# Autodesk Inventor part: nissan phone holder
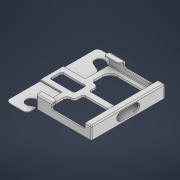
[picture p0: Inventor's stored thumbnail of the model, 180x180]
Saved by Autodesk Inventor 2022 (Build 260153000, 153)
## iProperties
Created: 2021-11
Part Number: nissan phone holder
Material: Všeobecné
Document SubType Name: Modeling
Designer: Fiji
Density: 1 g/cm^3
Appearance: Výchozí
Author: Fiji
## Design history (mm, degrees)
sketch "Náčrt1"
  geometry: L1 (0, 0)-(-22, 0); L2 (-22, 0)-(-22, -36); L3 (-22, -36)-(0, -36); L4 (0, -36)-(0, 0); L5 (-22, -11)-(-12.755, -5.4); L6 (-22, -21)-(-7.774, -14.716); C1 r 5 at (-14, -12); 2 further points
  constraints: 12 end point, 2 parallel, 2 point on line, 2 tangent, 1 centre point, 1 horizontal, 1 perpendicular
  dimensions: "d0" = 22 distance of L2.end L3.end; "d1" = 36 distance of L3.end L1.start; "d2" = 10 diameter of C1; "d3" = 12 distance from line of L1 C1.centre; "d4" = 8 distance from line of L2 C1.centre; "d5" = 11 distance from line of L1 L5.start; "d6" = 10 distance of L6.start L5.start
extrude "Vysunutí1" new body sketch "Náčrt1" distance "d7" = 0.6; taper "d8" = 0 deg
sketch "Náčrt2"
  geometry: L1 (-22, -36)-(0, -36) reference; L2 (0, -36)-(-22, -36); L3 (-22, -36)-(-22, -60); L4 (-22, -60)-(0, -60); L5 (0, -60)-(0, -36); 3 further points
  constraints: 8 end point, 2 parallel, 1 horizontal, 1 midpoint, 1 perpendicular
  dimensions: "d9" = 24 distance of L2.end L3.end
extrude "Vysunutí2" join sketch "Náčrt2" distance "d10" = 2; taper "d11" = 0 deg
node "Pracovní rovina1"
mirror "Zrcadlit1"
fillet "Zaoblení1" dims "d18" = 1, "d19" = 6, "d20" = 4
sketch "Náčrt5"
  geometry: L1 (-11.091, -2)-(35.091, -2) reference; L2 (0, 0)-(24, 0); L3 (24, 0)-(24, -2); L4 (24, -2)-(0, -2); L5 (0, -2)-(0, 0); 2 further points
  constraints: 8 end point, 2 parallel, 1 horizontal, 1 perpendicular, 1 point on line
  dimensions: "d28" = 24 distance of L3.end L4.end
extrude "Vysunutí5" join sketch "Náčrt5" distance "d29" = 58; taper "d30" = 0 deg
sketch "Náčrt6"
  geometry: L1 (0, 0)-(0, -2) reference; L2 (0, -2)-(24, -2) reference; L3 (24, -2)-(24, 0) reference; L4 (24, 0)-(0, 0) reference; L5 (-32, -2)-(56, -2) reference; L6 (12, -2)-(12, 0); L7 (-11.091, -2)-(-16.579, -2) reference; L8 (-26.5, -2)-(50.5, -2); L9 (50.5, -2)-(50.5, 11); L10 (50.5, 11)-(-26.5, 11); L11 (-26.5, 11)-(-26.5, -2); 5 further points
  constraints: 10 end point, 2 midpoint, 2 parallel, 1 horizontal, 1 perpendicular, 1 point on line, 1 other
  dimensions: "d31" = 13 distance between parallel lines of L10 L5; "d32" = 77 distance of L9.end L10.end
extrude "Vysunutí6" join sketch "Náčrt6" distance "d33" = 57.6; taper "d34" = 0 deg
sketch "Náčrt7"
  geometry: L1 (-24, 0)-(-24, -2) reference; L2 (0, 0)-(-24, 0) reference; L3 (0, -2)-(0, 0) reference; L4 (0, -2)-(26.5, -2) reference; L5 (26.5, -2)-(26.5, 11) reference; L6 (26.5, 11)-(-50.5, 11) reference; L7 (-50.5, 11)-(-50.5, -2) reference; L8 (-50.5, -2)-(-24, -2) reference; L9 (19.426, -1.4)-(29, -1.4) reference; L10 (-48.9, 9.4)-(24.9, 9.4); L11 (24.9, 9.4)-(24.9, -1.4); L12 (24.9, -1.4)-(-48.9, -1.4); L13 (-48.9, -1.4)-(-48.9, 9.4); 5 further points
  constraints: 8 end point, 2 parallel, 1 horizontal, 1 perpendicular, 1 point on line
  dimensions: "d35" = 1.6 distance between parallel lines of L5 L11; "d36" = 1.6 distance between parallel lines of L13 L7; "d37" = 1.6 distance between parallel lines of L6 L10; "d38" = 9.4 distance between parallel lines of L10 L2 (derived)
extrude "Vysunutí7" cut sketch "Náčrt7" distance "d39" = 56; taper "d40" = 0 deg
sketch "Náčrt8"
  geometry: L1 (-57.6, 1.6)-(-57.6, 26.5) reference; L2 (-57.6, 1.6)-(-1.6, 1.6) reference; L3 (-1.6, 1.6)-(-1.6, 26.5) reference; L4 (-57.6, 26.5)-(-1.6, 26.5) reference; L5 (-57.6, 50.5)-(-57.6, 75.4) reference; L6 (-57.6, 50.5)-(-1.6, 50.5) reference; L7 (-1.6, 50.5)-(-1.6, 75.4) reference; L8 (-57.6, 75.4)-(-1.6, 75.4) reference; L9 (-57.6, 1.6)-(-1.6, 1.6) reference; L10 (-57.6, 75.4)-(-1.6, 75.4) reference; L11 (-41.6, 1.6)-(-6.4, 1.6); L12 (-6.4, 1.6)-(-6.4, 75.4); L13 (-6.4, 75.4)-(-41.6, 75.4); L14 (-41.6, 75.4)-(-41.6, 1.6); L15 (0, 77)-(0, 0) reference; L16 (-57.6, 0)-(-57.6, 77) reference; L17 (-57.6, 1.6)-(-57.6, 26.5) reference; L18 (-57.6, 5.6)-(-41.6, 5.6); L19 (-57.6, 77)-(-57.6, 50.5) reference; L20 (-57.6, 71.4)-(-41.6, 71.4); L21 (-41.6, 1.6)-(-41.6, 0); L22 (-6.4, 1.6)-(-6.4, 0); L23 (-6.4, 75.4)-(-6.4, 77); L24 (-41.6, 75.4)-(-41.6, 77); L25 (0, 77)-(0, 0) reference; L26 (0, 77)-(-57.6, 77) reference; L27 (-57.6, 0)-(-57.6, 77) reference; L28 (0, 0)-(-57.6, 0) reference; 15 further points
  constraints: 20 end point, 6 point on line, 4 vertical, 3 perpendicular, 2 parallel, 1 horizontal
  dimensions: "d41" = 6.4 distance between parallel lines of L12 L15; "d42" = 16 distance between parallel lines of L14 L16; "d76" = 4 distance between parallel lines of L20 L10; "d77" = 4 distance between parallel lines of L2 L18
extrude "Vysunutí8" cut sketch "Náčrt8" distance "d43" = 6; taper "d44" = 0 deg
fillet "Zaoblení2" dims "d47" = 1.2, "d49" = 0.6
sketch "Náčrt10"
  geometry: L1 (-48.3, -1.4)-(-48.3, 8.8) reference; L2 (-24, -1.4)-(-48.3, -1.4) reference; L3 (-24, 0)-(-24, -1.4) reference; L4 (0, 0)-(-24, 0) reference; L5 (0, -1.4)-(0, 0) reference; L6 (24.3, -1.4)-(0, -1.4) reference; L7 (24.3, 8.8)-(24.3, -1.4) reference; L8 (-48.3, 8.8)-(24.3, 8.8) reference; L9 (-24, 0)-(-24, -1.4) reference; L10 (-24, 0)-(-49.3, 0); L11 (-49.3, 9.8)-(-49.3, -2) reference; L12 (0, 0)-(-24, 0) reference; L13 (0, 0)-(25.53, 0); L14 (25.3, -2)-(25.3, 9.8) reference; L15 (24.3, -1.4)-(0, -1.4) reference; L16 (24.3, -1.4)-(25.402, -1.4); L17 (-48.3, -1.4)-(-49.536, -1.4); 4 further points
  constraints: 8 end point, 3 horizontal, 1 perpendicular, 1 point on line
extrude "Vysunutí10" join sketch "Náčrt10" distance "d51" = 56; taper "d52" = 0 deg
fillet "Zaoblení3" dims "d101" = 0.2, "d102" = 2
sketch "Náčrt11"
  geometry: L1 (-32, -2)-(56, -2) reference; L2 (12, -2)-(12, 11); L3 (48.9, 11)-(-24.9, 11) reference; L4 (0, 9)-(24, 9); L5 (24, 9)-(24, 0); L6 (24, 0)-(0, 0); L7 (0, 0)-(0, 9); L8 (49.3, 11)-(-25.3, 11) reference; 1 further point
  constraints: 10 end point, 2 midpoint, 2 parallel, 1 horizontal, 1 perpendicular, 1 other
  dimensions: "d54" = 24 distance of L4.start L4.end; "d55" = 9 distance of L4.end L5.end; "d56" = 2 distance between parallel lines of L6 L1; "d57" = 2 distance between parallel lines of L4 L8 (derived)
extrude "Vysunutí11" cut sketch "Náčrt11" distance "d58" = 3; taper "d59" = 0 deg
fillet "Zaoblení5" dims "d78" = 0.6, "d83" = 3.2
sketch "Náčrt14"
  geometry: L1 (0, 60)-(0, 36) reference; L2 (0, 48)-(90.017, 48); L3 (4, 41.6)-(30, 41.6); L4 (30, 41.6)-(30, 54.4); L5 (30, 54.4)-(4, 54.4); L6 (4, 54.4)-(4, 41.6); L7 (36, 48)-(36, 35.6); L8 (36, 35.6)-(28.4, 35.6); L9 (28.4, 35.6)-(28.4, 15.5); L10 (28.4, 15.5)-(70.8, 15.5); L11 (70.8, 15.5)-(70.8, 48); L12 (22.4, 10.7)-(22.4, 36) reference; L13 (73.6, 9.5)-(78.8, 9.5) reference; L14 (78.8, 85.3)-(78.8, 10.7) reference; L15 (28.4, 60.4)-(28.4, 80.5); L16 (36, 48)-(36, 60.4); L17 (28.4, 80.5)-(70.8, 80.5); L18 (70.8, 80.5)-(70.8, 48); L19 (36, 60.4)-(28.4, 60.4); L20 (36, 45)-(70.8, 45); L21 (36, 51)-(70.8, 51); 4 further points
  constraints: 34 end point, 6 perpendicular, 6 symmetric about line, 4 point on line, 2 horizontal, 2 parallel, 1 midpoint, 1 vertical, 1 other
  dimensions: "d86" = 12.8 distance of L5.end L3.start; "d87" = 26 distance between parallel lines of L4 L6; "d88" = 4 distance between parallel lines of L1 L6; "d89" = 6 distance between parallel lines of L7 L4; "d90" = 6 distance between parallel lines of L8 L3; "d91" = 6 distance between parallel lines of L9 L12; "d92" = 6 distance between parallel lines of L13 L10; "d93" = 8 distance between parallel lines of L14 L11; "d100" = 3 distance between parallel lines of L20 L2
extrude "Vysunutí14" cut sketch "Náčrt14" extent not by distance; stored distance "d94" = 0; taper "d95" = 0 deg
fillet "Zaoblení6" dims "d96" = 4.5, "d97" = 8, "d98" = 4, "d99" = 2, "d103" = 0.6
node "Těleso1"
node "Promítnutá smyčka2"
node "Promítnutá smyčka3"
node "Promítnutá smyčka4"
node "Promítnutá smyčka5"
node "Promítnutá smyčka6"
node "Promítnutá smyčka12"
